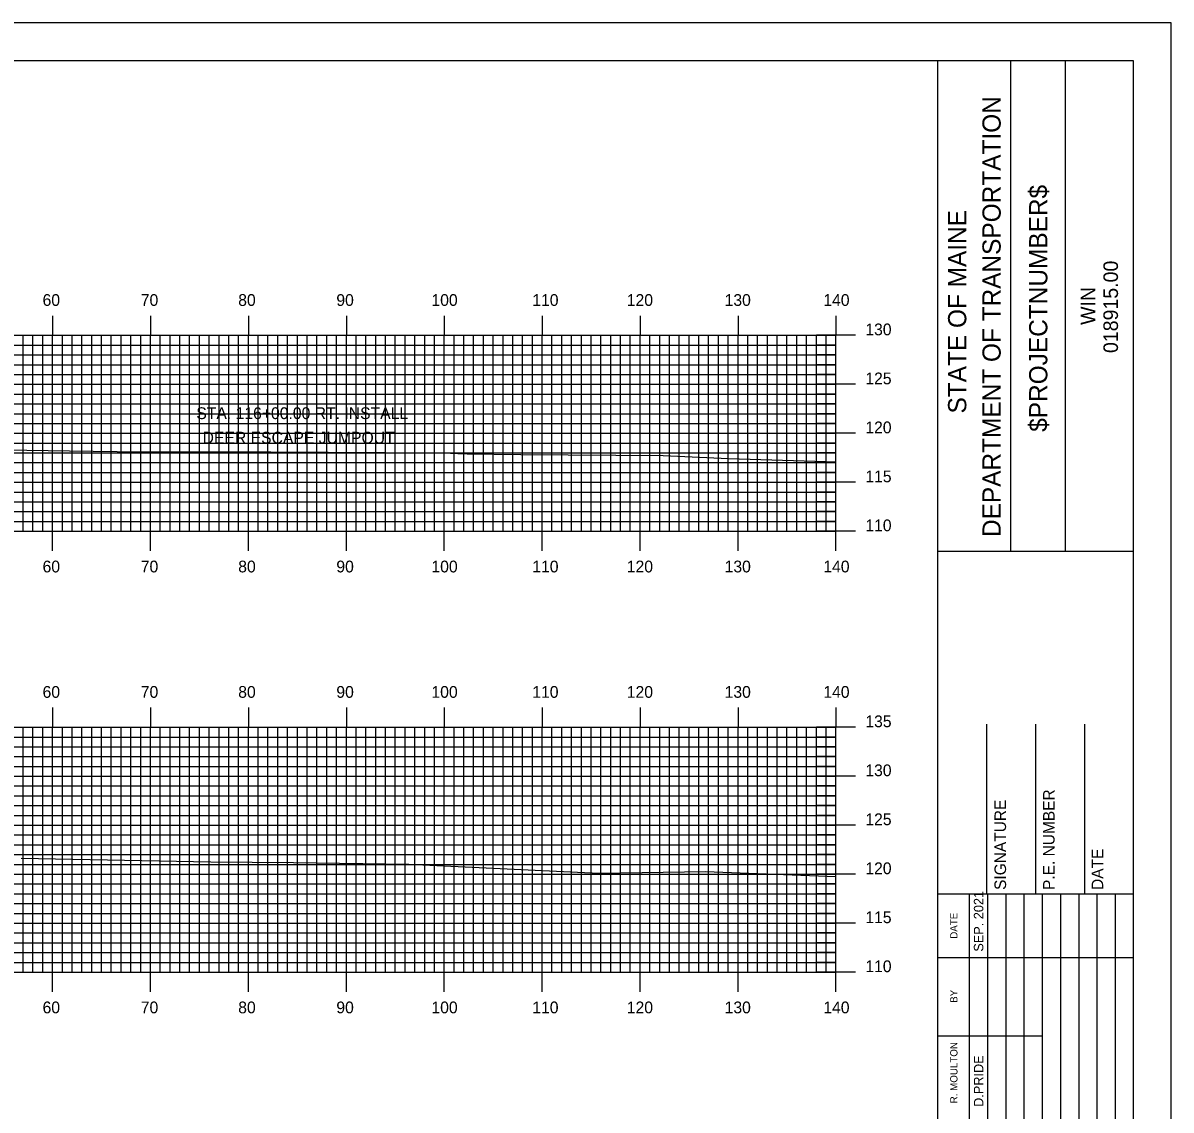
# Model space of a CAD drawing. Extents: x 1770842 to 1771185, y 442591 to 442811.
# Drawn here: x 1771064.5 to 1771181.8, y 442699.6 to 442810.5 of the extents above; entities that cross this region are included whole.
import ezdxf

# ---------------------------------------------------------------- set-up
doc = ezdxf.new("R2010")
doc.units = 0
for name, color, linetype in [('BORDER', 7, 'Continuous'), ('D_Text_Standard', 7, 'Continuous'), ('H_V ANNOTATION', 7, 'Continuous'), ('MAJOR', 7, 'Continuous'), ('MINOR', 7, 'Continuous'), ('PLOT BOUNDARY', 7, 'Continuous'), ('S_Roadway_Centerline', 7, 'Continuous')]:
    doc.layers.add(name, color=color, linetype=linetype)

msp = doc.modelspace()

# ---------------------------------------------------------------- linework, layer by layer
at = {"layer": 'BORDER'}
for p, q in [((1771157.95, 442596.67), (1771157.95, 442806.67)), ((1771165.41, 442756.66), (1771165.41, 442806.66)), ((1771171, 442756.66), (1771171, 442806.66)), ((1771157.96, 442756.65), (1771177.95, 442756.65)), ((1771162.95, 442721.67), (1771162.95, 442738.97)), ((1771167.95, 442721.67), (1771167.95, 442738.97)), ((1771172.95, 442721.67), (1771172.95, 442738.97)), ((1771157.95, 442721.67), (1771177.95, 442721.67))]:
    msp.add_line(p, q, dxfattribs=at)
msp.add_lwpolyline([(1770857.95, 442596.67), (1771177.95, 442596.67), (1771177.95, 442806.67), (1770857.95, 442806.67)], close=True, dxfattribs=at)
for points in [[(1771161.18, 442715.17), (1771161.18, 442721.67)], [(1771163.05, 442686.68), (1771163.05, 442721.67)], [(1771164.91, 442721.67), (1771164.91, 442686.68)], [(1771166.78, 442686.68), (1771166.78, 442721.67)], [(1771168.64, 442686.68), (1771168.64, 442721.67)], [(1771170.5, 442686.68), (1771170.5, 442721.67)], [(1771172.37, 442686.68), (1771172.37, 442721.67)], [(1771174.23, 442686.68), (1771174.23, 442721.67)], [(1771176.09, 442686.68), (1771176.09, 442721.67)], [(1771161.19, 442686.68), (1771161.19, 442720.26)], [(1771157.95, 442715.17), (1771177.95, 442715.17)], [(1771157.95, 442707.17), (1771161.19, 442707.17)], [(1771161.18, 442707.17), (1771168.64, 442707.17)]]:
    msp.add_lwpolyline(points, dxfattribs=at)
at = {"layer": 'MAJOR'}
for p, q in [((1771067.55, 442780.67), (1771067.55, 442778.67)), ((1771077.55, 442780.67), (1771077.55, 442778.67)), ((1771087.55, 442780.67), (1771087.55, 442778.67)), ((1771097.55, 442780.67), (1771097.55, 442778.67)), ((1771107.55, 442780.67), (1771107.55, 442778.67)), ((1771117.55, 442780.67), (1771117.55, 442778.67)), ((1771127.55, 442780.67), (1771127.55, 442778.67)), ((1771137.55, 442780.67), (1771137.55, 442778.67)), ((1771147.55, 442780.67), (1771147.55, 442778.67)), ((1770867.55, 442778.67), (1771147.55, 442778.67)), ((1770867.55, 442778.67), (1771147.55, 442778.67)), ((1771067.55, 442758.67), (1771067.55, 442778.67)), ((1771077.55, 442758.67), (1771077.55, 442778.67)), ((1771087.55, 442758.67), (1771087.55, 442778.67)), ((1771097.55, 442758.67), (1771097.55, 442778.67)), ((1771107.55, 442758.67), (1771107.55, 442778.67)), ((1771117.55, 442758.67), (1771117.55, 442778.67)), ((1771127.55, 442758.67), (1771127.55, 442778.67)), ((1771137.55, 442758.67), (1771137.55, 442778.67)), ((1771149.56, 442778.67), (1771145.55, 442778.67)), ((1771147.55, 442758.67), (1771147.55, 442778.67)), ((1771147.55, 442758.67), (1771147.55, 442778.67)), ((1770867.55, 442773.67), (1771147.55, 442773.67)), ((1771149.56, 442773.67), (1771145.55, 442773.67)), ((1770867.55, 442768.67), (1771147.55, 442768.67)), ((1771149.56, 442768.67), (1771145.55, 442768.67)), ((1770867.55, 442763.67), (1771147.55, 442763.67)), ((1771149.56, 442763.67), (1771145.55, 442763.67)), ((1770867.55, 442758.67), (1771147.55, 442758.67)), ((1770867.55, 442758.67), (1771147.55, 442758.67)), ((1771067.55, 442756.66), (1771067.55, 442758.67)), ((1771077.55, 442756.66), (1771077.55, 442758.67)), ((1771087.55, 442756.66), (1771087.55, 442758.67)), ((1771097.55, 442756.66), (1771097.55, 442758.67)), ((1771107.55, 442756.66), (1771107.55, 442758.67)), ((1771117.55, 442756.66), (1771117.55, 442758.67)), ((1771127.55, 442756.66), (1771127.55, 442758.67)), ((1771137.55, 442756.66), (1771137.55, 442758.67)), ((1771149.56, 442758.67), (1771145.55, 442758.67)), ((1771147.55, 442756.66), (1771147.55, 442758.67)), ((1771067.55, 442740.67), (1771067.55, 442738.67)), ((1771077.55, 442740.67), (1771077.55, 442738.67)), ((1771087.55, 442740.67), (1771087.55, 442738.67)), ((1771097.55, 442740.67), (1771097.55, 442738.67)), ((1771107.55, 442740.67), (1771107.55, 442738.67)), ((1771117.55, 442740.67), (1771117.55, 442738.67)), ((1771127.55, 442740.67), (1771127.55, 442738.67)), ((1771137.55, 442740.67), (1771137.55, 442738.67)), ((1771147.55, 442740.67), (1771147.55, 442738.67)), ((1770867.55, 442738.67), (1771147.55, 442738.67)), ((1770867.55, 442738.67), (1771147.55, 442738.67)), ((1771067.55, 442713.67), (1771067.55, 442738.67)), ((1771077.55, 442713.67), (1771077.55, 442738.67)), ((1771087.55, 442713.67), (1771087.55, 442738.67)), ((1771097.55, 442713.67), (1771097.55, 442738.67)), ((1771107.55, 442713.67), (1771107.55, 442738.67)), ((1771117.55, 442713.67), (1771117.55, 442738.67)), ((1771127.55, 442713.67), (1771127.55, 442738.67)), ((1771137.55, 442713.67), (1771137.55, 442738.67)), ((1771149.56, 442738.67), (1771145.55, 442738.67)), ((1771147.55, 442713.67), (1771147.55, 442738.67)), ((1771147.55, 442713.67), (1771147.55, 442738.67)), ((1770867.55, 442733.67), (1771147.55, 442733.67)), ((1771149.56, 442733.67), (1771145.55, 442733.67)), ((1770867.55, 442728.67), (1771147.55, 442728.67)), ((1771149.56, 442728.67), (1771145.55, 442728.67)), ((1770867.55, 442723.67), (1771147.55, 442723.67)), ((1771149.56, 442723.67), (1771145.55, 442723.67)), ((1770867.55, 442718.67), (1771147.55, 442718.67)), ((1771149.56, 442718.67), (1771145.55, 442718.67)), ((1770867.55, 442713.67), (1771147.55, 442713.67)), ((1770867.55, 442713.67), (1771147.55, 442713.67)), ((1771067.55, 442711.66), (1771067.55, 442713.67)), ((1771077.55, 442711.66), (1771077.55, 442713.67)), ((1771087.55, 442711.66), (1771087.55, 442713.67)), ((1771097.55, 442711.66), (1771097.55, 442713.67)), ((1771107.55, 442711.66), (1771107.55, 442713.67)), ((1771117.55, 442711.66), (1771117.55, 442713.67)), ((1771127.55, 442711.66), (1771127.55, 442713.67)), ((1771137.55, 442711.66), (1771137.55, 442713.67)), ((1771149.56, 442713.67), (1771145.55, 442713.67)), ((1771147.55, 442711.66), (1771147.55, 442713.67))]:
    msp.add_line(p, q, dxfattribs=at)
at = {"layer": 'MINOR'}
for p, q in [((1770867.55, 442777.67), (1771147.55, 442777.67)), ((1771064.55, 442758.67), (1771064.55, 442778.67)), ((1771065.55, 442758.67), (1771065.55, 442778.67)), ((1771066.55, 442758.67), (1771066.55, 442778.67)), ((1771068.55, 442758.67), (1771068.55, 442778.67)), ((1771069.55, 442758.67), (1771069.55, 442778.67)), ((1771070.55, 442758.67), (1771070.55, 442778.67)), ((1771071.55, 442758.67), (1771071.55, 442778.67)), ((1771072.55, 442758.67), (1771072.55, 442778.67)), ((1771073.55, 442758.67), (1771073.55, 442778.67)), ((1771074.55, 442758.67), (1771074.55, 442778.67)), ((1771075.55, 442758.67), (1771075.55, 442778.67)), ((1771076.55, 442758.67), (1771076.55, 442778.67)), ((1771078.55, 442758.67), (1771078.55, 442778.67)), ((1771079.55, 442758.67), (1771079.55, 442778.67)), ((1771080.55, 442758.67), (1771080.55, 442778.67)), ((1771081.55, 442758.67), (1771081.55, 442778.67)), ((1771082.55, 442758.67), (1771082.55, 442778.67)), ((1771083.55, 442758.67), (1771083.55, 442778.67)), ((1771084.55, 442758.67), (1771084.55, 442778.67)), ((1771085.55, 442758.67), (1771085.55, 442778.67)), ((1771086.55, 442758.67), (1771086.55, 442778.67)), ((1771088.55, 442758.67), (1771088.55, 442778.67)), ((1771089.55, 442758.67), (1771089.55, 442778.67)), ((1771090.55, 442758.67), (1771090.55, 442778.67)), ((1771091.55, 442758.67), (1771091.55, 442778.67)), ((1771092.55, 442758.67), (1771092.55, 442778.67)), ((1771093.55, 442758.67), (1771093.55, 442778.67)), ((1771094.55, 442758.67), (1771094.55, 442778.67)), ((1771095.55, 442758.67), (1771095.55, 442778.67)), ((1771096.55, 442758.67), (1771096.55, 442778.67)), ((1771098.55, 442758.67), (1771098.55, 442778.67)), ((1771099.55, 442758.67), (1771099.55, 442778.67)), ((1771100.55, 442758.67), (1771100.55, 442778.67)), ((1771101.55, 442758.67), (1771101.55, 442778.67)), ((1771102.55, 442758.67), (1771102.55, 442778.67)), ((1771103.55, 442758.67), (1771103.55, 442778.67)), ((1771104.55, 442758.67), (1771104.55, 442778.67)), ((1771105.55, 442758.67), (1771105.55, 442778.67)), ((1771106.55, 442758.67), (1771106.55, 442778.67)), ((1771108.55, 442758.67), (1771108.55, 442778.67)), ((1771109.55, 442758.67), (1771109.55, 442778.67)), ((1771110.55, 442758.67), (1771110.55, 442778.67)), ((1771111.55, 442758.67), (1771111.55, 442778.67)), ((1771112.55, 442758.67), (1771112.55, 442778.67)), ((1771113.55, 442758.67), (1771113.55, 442778.67)), ((1771114.55, 442758.67), (1771114.55, 442778.67)), ((1771115.55, 442758.67), (1771115.55, 442778.67)), ((1771116.55, 442758.67), (1771116.55, 442778.67)), ((1771118.55, 442758.67), (1771118.55, 442778.67)), ((1771119.55, 442758.67), (1771119.55, 442778.67)), ((1771120.55, 442758.67), (1771120.55, 442778.67)), ((1771121.55, 442758.67), (1771121.55, 442778.67)), ((1771122.55, 442758.67), (1771122.55, 442778.67)), ((1771123.55, 442758.67), (1771123.55, 442778.67)), ((1771124.55, 442758.67), (1771124.55, 442778.67)), ((1771125.55, 442758.67), (1771125.55, 442778.67)), ((1771126.55, 442758.67), (1771126.55, 442778.67)), ((1771128.55, 442758.67), (1771128.55, 442778.67)), ((1771129.55, 442758.67), (1771129.55, 442778.67)), ((1771130.55, 442758.67), (1771130.55, 442778.67)), ((1771131.55, 442758.67), (1771131.55, 442778.67)), ((1771132.55, 442758.67), (1771132.55, 442778.67)), ((1771133.55, 442758.67), (1771133.55, 442778.67)), ((1771134.55, 442758.67), (1771134.55, 442778.67)), ((1771135.55, 442758.67), (1771135.55, 442778.67)), ((1771136.55, 442758.67), (1771136.55, 442778.67)), ((1771138.55, 442758.67), (1771138.55, 442778.67)), ((1771139.55, 442758.67), (1771139.55, 442778.67)), ((1771140.55, 442758.67), (1771140.55, 442778.67)), ((1771141.55, 442758.67), (1771141.55, 442778.67)), ((1771142.55, 442758.67), (1771142.55, 442778.67)), ((1771143.55, 442758.67), (1771143.55, 442778.67)), ((1771144.55, 442758.67), (1771144.55, 442778.67)), ((1771145.55, 442758.67), (1771145.55, 442778.67)), ((1771147.55, 442777.67), (1771145.55, 442777.67)), ((1771146.55, 442758.67), (1771146.55, 442778.67)), ((1770867.55, 442776.67), (1771147.55, 442776.67)), ((1771147.55, 442776.67), (1771145.55, 442776.67)), ((1770867.55, 442775.67), (1771147.55, 442775.67)), ((1771147.55, 442775.67), (1771145.55, 442775.67)), ((1770867.55, 442774.67), (1771147.55, 442774.67)), ((1771147.55, 442774.67), (1771145.55, 442774.67)), ((1770867.55, 442772.67), (1771147.55, 442772.67)), ((1771147.55, 442772.67), (1771145.55, 442772.67)), ((1770867.55, 442771.67), (1771147.55, 442771.67)), ((1770867.55, 442770.67), (1771147.55, 442770.67)), ((1771147.55, 442771.67), (1771145.55, 442771.67)), ((1771147.55, 442770.67), (1771145.55, 442770.67)), ((1770867.55, 442769.67), (1771147.55, 442769.67)), ((1771147.55, 442769.67), (1771145.55, 442769.67)), ((1770867.55, 442767.67), (1771147.55, 442767.67)), ((1771147.55, 442767.67), (1771145.55, 442767.67)), ((1770867.55, 442766.67), (1771147.55, 442766.67)), ((1771147.55, 442766.67), (1771145.55, 442766.67)), ((1770867.55, 442765.67), (1771147.55, 442765.67)), ((1770867.55, 442764.67), (1771147.55, 442764.67)), ((1771147.55, 442765.67), (1771145.55, 442765.67)), ((1771147.55, 442764.67), (1771145.55, 442764.67)), ((1770867.55, 442762.67), (1771147.55, 442762.67)), ((1771147.55, 442762.67), (1771145.55, 442762.67)), ((1770867.55, 442761.67), (1771147.55, 442761.67)), ((1771147.55, 442761.67), (1771145.55, 442761.67)), ((1770867.55, 442760.67), (1771147.55, 442760.67)), ((1771147.55, 442760.67), (1771145.55, 442760.67)), ((1770867.55, 442759.67), (1771147.55, 442759.67)), ((1771147.55, 442759.67), (1771145.55, 442759.67)), ((1771064.55, 442713.67), (1771064.55, 442738.67)), ((1771065.55, 442713.67), (1771065.55, 442738.67)), ((1771066.55, 442713.67), (1771066.55, 442738.67)), ((1771068.55, 442713.67), (1771068.55, 442738.67)), ((1771069.55, 442713.67), (1771069.55, 442738.67)), ((1771070.55, 442713.67), (1771070.55, 442738.67)), ((1771071.55, 442713.67), (1771071.55, 442738.67)), ((1771072.55, 442713.67), (1771072.55, 442738.67)), ((1771073.55, 442713.67), (1771073.55, 442738.67)), ((1771074.55, 442713.67), (1771074.55, 442738.67)), ((1771075.55, 442713.67), (1771075.55, 442738.67)), ((1771076.55, 442713.67), (1771076.55, 442738.67)), ((1771078.55, 442713.67), (1771078.55, 442738.67)), ((1771079.55, 442713.67), (1771079.55, 442738.67)), ((1771080.55, 442713.67), (1771080.55, 442738.67)), ((1771081.55, 442713.67), (1771081.55, 442738.67)), ((1771082.55, 442713.67), (1771082.55, 442738.67)), ((1771083.55, 442713.67), (1771083.55, 442738.67)), ((1771084.55, 442713.67), (1771084.55, 442738.67)), ((1771085.55, 442713.67), (1771085.55, 442738.67)), ((1771086.55, 442713.67), (1771086.55, 442738.67)), ((1771088.55, 442713.67), (1771088.55, 442738.67)), ((1771089.55, 442713.67), (1771089.55, 442738.67)), ((1771090.55, 442713.67), (1771090.55, 442738.67)), ((1771091.55, 442713.67), (1771091.55, 442738.67)), ((1771092.55, 442713.67), (1771092.55, 442738.67)), ((1771093.55, 442713.67), (1771093.55, 442738.67)), ((1771094.55, 442713.67), (1771094.55, 442738.67)), ((1771095.55, 442713.67), (1771095.55, 442738.67)), ((1771096.55, 442713.67), (1771096.55, 442738.67)), ((1771098.55, 442713.67), (1771098.55, 442738.67)), ((1771099.55, 442713.67), (1771099.55, 442738.67)), ((1771100.55, 442713.67), (1771100.55, 442738.67)), ((1771101.55, 442713.67), (1771101.55, 442738.67)), ((1771102.55, 442713.67), (1771102.55, 442738.67)), ((1771103.55, 442713.67), (1771103.55, 442738.67)), ((1771104.55, 442713.67), (1771104.55, 442738.67)), ((1771105.55, 442713.67), (1771105.55, 442738.67)), ((1771106.55, 442713.67), (1771106.55, 442738.67)), ((1771108.55, 442713.67), (1771108.55, 442738.67)), ((1771109.55, 442713.67), (1771109.55, 442738.67)), ((1771110.55, 442713.67), (1771110.55, 442738.67)), ((1771111.55, 442713.67), (1771111.55, 442738.67)), ((1771112.55, 442713.67), (1771112.55, 442738.67)), ((1771113.55, 442713.67), (1771113.55, 442738.67)), ((1771114.55, 442713.67), (1771114.55, 442738.67)), ((1771115.55, 442713.67), (1771115.55, 442738.67)), ((1771116.55, 442713.67), (1771116.55, 442738.67)), ((1771118.55, 442713.67), (1771118.55, 442738.67)), ((1771119.55, 442713.67), (1771119.55, 442738.67)), ((1771120.55, 442713.67), (1771120.55, 442738.67)), ((1771121.55, 442713.67), (1771121.55, 442738.67)), ((1771122.55, 442713.67), (1771122.55, 442738.67)), ((1771123.55, 442713.67), (1771123.55, 442738.67)), ((1771124.55, 442713.67), (1771124.55, 442738.67)), ((1771125.55, 442713.67), (1771125.55, 442738.67)), ((1771126.55, 442713.67), (1771126.55, 442738.67)), ((1771128.55, 442713.67), (1771128.55, 442738.67)), ((1771129.55, 442713.67), (1771129.55, 442738.67)), ((1771130.55, 442713.67), (1771130.55, 442738.67)), ((1771131.55, 442713.67), (1771131.55, 442738.67)), ((1771132.55, 442713.67), (1771132.55, 442738.67)), ((1771133.55, 442713.67), (1771133.55, 442738.67)), ((1771134.55, 442713.67), (1771134.55, 442738.67)), ((1771135.55, 442713.67), (1771135.55, 442738.67)), ((1771136.55, 442713.67), (1771136.55, 442738.67)), ((1771138.55, 442713.67), (1771138.55, 442738.67)), ((1771139.55, 442713.67), (1771139.55, 442738.67)), ((1771140.55, 442713.67), (1771140.55, 442738.67)), ((1771141.55, 442713.67), (1771141.55, 442738.67)), ((1771142.55, 442713.67), (1771142.55, 442738.67)), ((1771143.55, 442713.67), (1771143.55, 442738.67)), ((1771144.55, 442713.67), (1771144.55, 442738.67)), ((1771145.55, 442713.67), (1771145.55, 442738.67)), ((1771146.55, 442713.67), (1771146.55, 442738.67)), ((1770867.55, 442737.67), (1771147.55, 442737.67)), ((1770867.55, 442736.67), (1771147.55, 442736.67)), ((1771147.55, 442737.67), (1771145.55, 442737.67)), ((1771147.55, 442736.67), (1771145.55, 442736.67)), ((1770867.55, 442735.67), (1771147.55, 442735.67)), ((1771147.55, 442735.67), (1771145.55, 442735.67)), ((1770867.55, 442734.67), (1771147.55, 442734.67)), ((1771147.55, 442734.67), (1771145.55, 442734.67)), ((1770867.55, 442732.67), (1771147.55, 442732.67)), ((1771147.55, 442732.67), (1771145.55, 442732.67)), ((1770867.55, 442731.67), (1771147.55, 442731.67)), ((1770867.55, 442730.67), (1771147.55, 442730.67)), ((1771147.55, 442731.67), (1771145.55, 442731.67)), ((1771147.55, 442730.67), (1771145.55, 442730.67)), ((1770867.55, 442729.67), (1771147.55, 442729.67)), ((1771147.55, 442729.67), (1771145.55, 442729.67)), ((1770867.55, 442727.67), (1771147.55, 442727.67)), ((1771147.55, 442727.67), (1771145.55, 442727.67)), ((1770867.55, 442726.67), (1771147.55, 442726.67)), ((1771147.55, 442726.67), (1771145.55, 442726.67)), ((1770867.55, 442725.67), (1771147.55, 442725.67)), ((1771147.55, 442725.67), (1771145.55, 442725.67)), ((1770867.55, 442724.67), (1771147.55, 442724.67)), ((1771147.55, 442724.67), (1771145.55, 442724.67)), ((1770867.55, 442722.67), (1771147.55, 442722.67)), ((1771147.55, 442722.67), (1771145.55, 442722.67)), ((1770867.55, 442721.67), (1771147.55, 442721.67)), ((1771147.55, 442721.67), (1771145.55, 442721.67)), ((1770867.55, 442720.67), (1771147.55, 442720.67)), ((1771147.55, 442720.67), (1771145.55, 442720.67)), ((1770867.55, 442719.67), (1771147.55, 442719.67)), ((1771147.55, 442719.67), (1771145.55, 442719.67)), ((1770867.55, 442717.67), (1771147.55, 442717.67)), ((1770867.55, 442716.67), (1771147.55, 442716.67)), ((1771147.55, 442717.67), (1771145.55, 442717.67)), ((1771147.55, 442716.67), (1771145.55, 442716.67)), ((1770867.55, 442715.67), (1771147.55, 442715.67)), ((1771147.55, 442715.67), (1771145.55, 442715.67)), ((1770867.55, 442714.67), (1771147.55, 442714.67)), ((1771147.55, 442714.67), (1771145.55, 442714.67))]:
    msp.add_line(p, q, dxfattribs=at)
at = {"layer": 'PLOT BOUNDARY'}
msp.add_lwpolyline([(1770841.77, 442590.55), (1771181.77, 442590.55), (1771181.77, 442810.55), (1770841.77, 442810.55)], close=True, dxfattribs=at)
at = {"layer": 'S_Roadway_Centerline'}
for points in [[(1771049.65, 442767.18), (1771069.27, 442766.89), (1771076.56, 442766.78), (1771089.85, 442766.79), (1771107.43, 442766.67), (1771108.93, 442766.61), (1771109.89, 442766.57), (1771115.37, 442766.52), (1771129.92, 442766.39), (1771136.56, 442766.08), (1771144.29, 442765.87), (1771147.55, 442765.77)], [(1771064.35, 442725.29), (1771083.72, 442724.92), (1771092.14, 442724.87), (1771103.94, 442724.7), (1771121.86, 442723.85), (1771123.43, 442723.78), (1771134.23, 442723.93), (1771143.07, 442723.6), (1771147.55, 442723.43)]]:
    msp.add_lwpolyline(points, dxfattribs=at)

# ---------------------------------------------------------------- texts
at = {"layer": 'BORDER'}
for s, height, p in [('DEPARTMENT OF TRANSPORTATION', 1.8635, (1771164.37, 442758.08)), ('$PROJECTNUMBER$', 1.8635, (1771169.14, 442768.82)), ('STATE OF MAINE', 1.8635, (1771160.86, 442770.69)), ('018915.00', 1.491, (1771176.35, 442776.86)), ('WIN', 1.491, (1771174.03, 442779.73)), ('P.E. NUMBER', 1.1811, (1771169.88, 442722.06)), ('SIGNATURE', 1.181, (1771164.92, 442722.06)), ('DATE', 1.181, (1771174.84, 442722.06)), ('SEP. 2021', 0.969, (1771162.6, 442715.76)), ('DATE', 0.743, (1771159.96, 442717.08)), ('BY', 0.743, (1771159.96, 442710.54)), ('R. MOULTON', 0.745, (1771159.96, 442700.28)), ('D.PRIDE', 0.969, (1771162.6, 442699.92))]:
    msp.add_text(s, height=height, rotation=90, dxfattribs=at).set_placement(p)
at = {"layer": 'D_Text_Standard'}
for s, p in [('STA. 116+00.00 RT. INSTALL ', (1771082.23, 442770.12)), ('DEER ESCAPE JUMPOUT', (1771082.87, 442767.62))]:
    msp.add_text(s, height=1.2, dxfattribs=at).set_placement(p)
at = {"layer": 'H_V ANNOTATION'}
for s, p in [('60', (1771066.53, 442781.67)), ('70', (1771076.56, 442781.67)), ('80', (1771086.51, 442781.67)), ('90', (1771096.53, 442781.67)), ('100', (1771106.24, 442781.67)), ('110', (1771116.54, 442781.67)), ('120', (1771126.19, 442781.67)), ('130', (1771136.18, 442781.67)), ('140', (1771146.26, 442781.67)), ('130', (1771150.55, 442778.67)), ('125', (1771150.55, 442773.67)), ('120', (1771150.55, 442768.67)), ('115', (1771150.55, 442763.67)), ('110', (1771150.55, 442758.67)), ('60', (1771066.53, 442754.47)), ('70', (1771076.56, 442754.47)), ('80', (1771086.51, 442754.47)), ('90', (1771096.53, 442754.47)), ('100', (1771106.24, 442754.47)), ('110', (1771116.54, 442754.47)), ('120', (1771126.19, 442754.47)), ('130', (1771136.18, 442754.47)), ('140', (1771146.26, 442754.47)), ('60', (1771066.53, 442741.67)), ('70', (1771076.56, 442741.67)), ('80', (1771086.51, 442741.67)), ('90', (1771096.53, 442741.67)), ('100', (1771106.24, 442741.67)), ('110', (1771116.54, 442741.67)), ('120', (1771126.19, 442741.67)), ('130', (1771136.18, 442741.67)), ('140', (1771146.26, 442741.67)), ('135', (1771150.55, 442738.67)), ('130', (1771150.55, 442733.67)), ('125', (1771150.55, 442728.67)), ('120', (1771150.55, 442723.67)), ('115', (1771150.55, 442718.67)), ('110', (1771150.55, 442713.67)), ('60', (1771066.53, 442709.47)), ('70', (1771076.56, 442709.47)), ('80', (1771086.51, 442709.47)), ('90', (1771096.53, 442709.47)), ('100', (1771106.24, 442709.47)), ('110', (1771116.54, 442709.47)), ('120', (1771126.19, 442709.47)), ('130', (1771136.18, 442709.47)), ('140', (1771146.26, 442709.47))]:
    msp.add_text(s, height=1.2, dxfattribs=at).set_placement(p)

doc.saveas('drawing.dxf')
